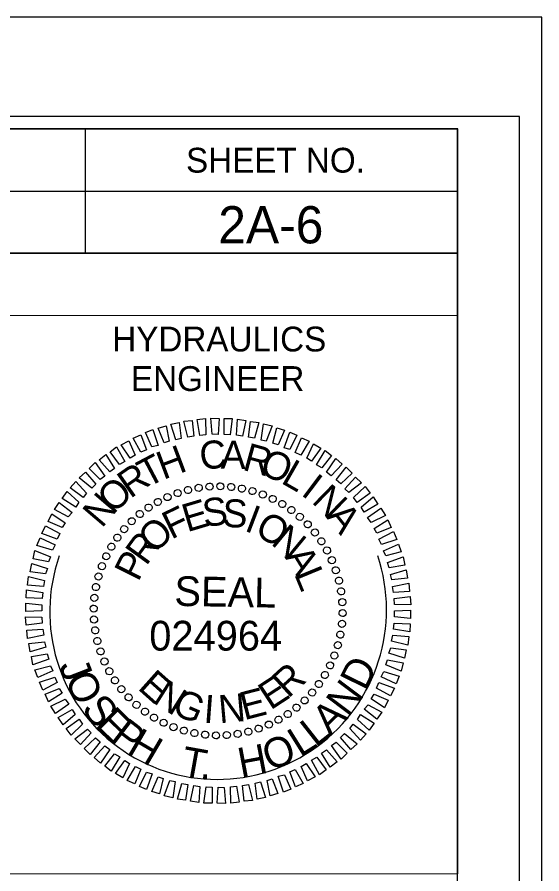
# Model space of a CAD drawing. Extents: x 1640342 to 1730599, y 538663 to 843747.
# Drawn here: x 1730156.25 to 1730177.39, y 539096.41 to 539130.92 of the extents above; entities that cross this region are included whole.
import ezdxf

# ---------------------------------------------------------------- set-up
doc = ezdxf.new("R2010")
doc.units = 0
for name, color, linetype in [('Sheet Data Field CELL', 7, 'Continuous'), ('Sheet PE Seal Cell', 7, 'Continuous'), ('Sheet Plan CELL', 7, 'Continuous'), ('Sheet Plan Layout CELL', 7, 'Continuous'), ('Sheet Plot Border Inside CELL', 7, 'Continuous'), ('Sheet Plot Border Outside CELL', 7, 'Continuous')]:
    doc.layers.add(name, color=color, linetype=linetype)

msp = doc.modelspace()

# ---------------------------------------------------------------- linework, layer by layer
at = {"layer": 'Sheet PE Seal Cell'}
for p, q in [((1730163.999, 539112.014), (1730163.999, 539112.014)), ((1730164.439, 539112.024), (1730164.439, 539112.024)), ((1730164.879, 539111.994), (1730164.879, 539111.994)), ((1730162.709, 539111.754), (1730162.709, 539111.754)), ((1730163.129, 539111.874), (1730163.129, 539111.874)), ((1730163.569, 539111.954), (1730163.569, 539111.954)), ((1730165.309, 539111.924), (1730165.309, 539111.924)), ((1730165.729, 539111.834), (1730165.729, 539111.834)), ((1730166.149, 539111.694), (1730166.149, 539111.694)), ((1730161.919, 539111.394), (1730161.919, 539111.394)), ((1730162.309, 539111.594), (1730162.309, 539111.594)), ((1730166.549, 539111.514), (1730166.549, 539111.514)), ((1730166.939, 539111.314), (1730166.939, 539111.314)), ((1730161.539, 539111.164), (1730161.539, 539111.164)), ((1730167.299, 539111.064), (1730167.299, 539111.064)), ((1730160.859, 539110.614), (1730160.859, 539110.614)), ((1730161.189, 539110.914), (1730161.189, 539110.914)), ((1730167.649, 539110.794), (1730167.649, 539110.794)), ((1730160.559, 539110.304), (1730160.559, 539110.304)), ((1730167.959, 539110.494), (1730167.959, 539110.494)), ((1730160.289, 539109.954), (1730160.289, 539109.954)), ((1730168.259, 539110.164), (1730168.259, 539110.164)), ((1730160.039, 539109.594), (1730160.039, 539109.594)), ((1730168.509, 539109.814), (1730168.509, 539109.814)), ((1730168.739, 539109.434), (1730168.739, 539109.434)), ((1730159.839, 539109.204), (1730159.839, 539109.204)), ((1730168.939, 539109.044), (1730168.939, 539109.044)), ((1730159.659, 539108.804), (1730159.659, 539108.804)), ((1730169.099, 539108.644), (1730169.099, 539108.644)), ((1730159.519, 539108.384), (1730159.519, 539108.384)), ((1730169.219, 539108.224), (1730169.219, 539108.224)), ((1730159.429, 539107.964), (1730159.429, 539107.964)), ((1730159.359, 539107.534), (1730159.359, 539107.534)), ((1730169.299, 539107.784), (1730169.299, 539107.784)), ((1730169.359, 539107.354), (1730169.359, 539107.354)), ((1730159.329, 539107.094), (1730159.329, 539107.094)), ((1730169.369, 539106.914), (1730169.369, 539106.914)), ((1730159.339, 539106.654), (1730159.339, 539106.654)), ((1730169.339, 539106.474), (1730169.339, 539106.474)), ((1730159.399, 539106.224), (1730159.399, 539106.224)), ((1730159.479, 539105.784), (1730159.479, 539105.784)), ((1730169.269, 539106.044), (1730169.269, 539106.044)), ((1730169.179, 539105.624), (1730169.179, 539105.624)), ((1730159.599, 539105.364), (1730159.599, 539105.364)), ((1730169.039, 539105.204), (1730169.039, 539105.204)), ((1730159.759, 539104.964), (1730159.759, 539104.964)), ((1730168.859, 539104.804), (1730168.859, 539104.804)), ((1730159.959, 539104.574), (1730159.959, 539104.574)), ((1730168.659, 539104.414), (1730168.659, 539104.414)), ((1730160.189, 539104.194), (1730160.189, 539104.194)), ((1730168.409, 539104.054), (1730168.409, 539104.054)), ((1730160.439, 539103.844), (1730160.439, 539103.844)), ((1730160.739, 539103.514), (1730160.739, 539103.514)), ((1730167.839, 539103.394), (1730167.839, 539103.394)), ((1730168.139, 539103.704), (1730168.139, 539103.704)), ((1730161.049, 539103.214), (1730161.049, 539103.214)), ((1730167.509, 539103.094), (1730167.509, 539103.094)), ((1730161.399, 539102.944), (1730161.399, 539102.944)), ((1730161.759, 539102.694), (1730161.759, 539102.694)), ((1730167.159, 539102.844), (1730167.159, 539102.844)), ((1730162.149, 539102.494), (1730162.149, 539102.494)), ((1730166.389, 539102.414), (1730166.389, 539102.414)), ((1730166.779, 539102.614), (1730166.779, 539102.614)), ((1730162.549, 539102.314), (1730162.549, 539102.314)), ((1730162.969, 539102.174), (1730162.969, 539102.174)), ((1730163.389, 539102.084), (1730163.389, 539102.084)), ((1730163.819, 539102.014), (1730163.819, 539102.014)), ((1730164.259, 539101.984), (1730164.259, 539101.984)), ((1730164.699, 539101.994), (1730164.699, 539101.994)), ((1730165.129, 539102.054), (1730165.129, 539102.054)), ((1730165.569, 539102.134), (1730165.569, 539102.134)), ((1730165.989, 539102.254), (1730165.989, 539102.254))]:
    msp.add_line(p, q, dxfattribs=at)
for points in [[(1730164.109, 539114.114), (1730164.059, 539114.764), (1730164.389, 539114.754), (1730164.349, 539114.104)], [(1730164.589, 539114.104), (1730164.589, 539114.754), (1730164.919, 539114.744), (1730164.829, 539114.094)], [(1730162.169, 539113.764), (1730161.939, 539114.364), (1730162.249, 539114.454), (1730162.379, 539113.834)], [(1730162.649, 539113.894), (1730162.439, 539114.524), (1730162.779, 539114.594), (1730162.859, 539113.944)], [(1730163.129, 539114.004), (1730162.969, 539114.644), (1730163.299, 539114.674), (1730163.369, 539114.034)], [(1730163.609, 539114.064), (1730163.499, 539114.704), (1730163.839, 539114.744), (1730163.849, 539114.094)], [(1730165.089, 539114.074), (1730165.129, 539114.724), (1730165.459, 539114.664), (1730165.329, 539114.034)], [(1730165.569, 539113.994), (1730165.659, 539114.634), (1730165.989, 539114.584), (1730165.809, 539113.964)], [(1730166.079, 539113.884), (1730166.179, 539114.534), (1730166.519, 539114.454), (1730166.289, 539113.834)], [(1730161.239, 539113.394), (1730160.919, 539113.954), (1730161.229, 539114.094), (1730161.459, 539113.484)], [(1730161.679, 539113.604), (1730161.419, 539114.184), (1730161.719, 539114.304), (1730161.929, 539113.664)], [(1730166.559, 539113.754), (1730166.709, 539114.374), (1730167.019, 539114.274), (1730166.769, 539113.684)], [(1730167.009, 539113.574), (1730167.239, 539114.204), (1730167.519, 539114.084), (1730167.239, 539113.504)], [(1730160.809, 539113.154), (1730160.439, 539113.694), (1730160.749, 539113.854), (1730160.999, 539113.274)], [(1730167.459, 539113.384), (1730167.709, 539113.974), (1730168.019, 539113.834), (1730167.679, 539113.274)], [(1730167.919, 539113.154), (1730168.189, 539113.724), (1730168.489, 539113.554), (1730168.109, 539113.034)], [(1730160.369, 539112.904), (1730159.999, 539113.414), (1730160.259, 539113.604), (1730160.589, 539113.024)], [(1730168.309, 539112.884), (1730168.659, 539113.464), (1730168.919, 539113.254), (1730168.529, 539112.764)], [(1730159.989, 539112.604), (1730159.559, 539113.084), (1730159.829, 539113.294), (1730160.179, 539112.734)], [(1730168.719, 539112.584), (1730169.089, 539113.134), (1730169.349, 539112.914), (1730168.909, 539112.444)], [(1730159.589, 539112.294), (1730159.149, 539112.734), (1730159.389, 539112.974), (1730159.779, 539112.434)], [(1730169.099, 539112.274), (1730169.509, 539112.794), (1730169.749, 539112.554), (1730169.289, 539112.124)], [(1730159.259, 539111.944), (1730158.749, 539112.354), (1730158.999, 539112.584), (1730159.419, 539112.104)], [(1730169.459, 539111.924), (1730169.889, 539112.394), (1730170.129, 539112.154), (1730169.609, 539111.764)], [(1730158.909, 539111.564), (1730158.389, 539111.954), (1730158.609, 539112.214), (1730159.049, 539111.744)], [(1730169.809, 539111.564), (1730170.269, 539112.014), (1730170.479, 539111.744), (1730169.949, 539111.364)], [(1730158.609, 539111.184), (1730158.069, 539111.524), (1730158.259, 539111.814), (1730158.739, 539111.374)], [(1730158.309, 539110.784), (1730157.749, 539111.084), (1730157.949, 539111.364), (1730158.469, 539110.964)], [(1730170.109, 539111.174), (1730170.599, 539111.594), (1730170.789, 539111.304), (1730170.229, 539110.984)], [(1730170.369, 539110.764), (1730170.899, 539111.144), (1730171.089, 539110.844), (1730170.509, 539110.564)], [(1730158.069, 539110.354), (1730157.499, 539110.604), (1730157.649, 539110.914), (1730158.189, 539110.544)], [(1730170.629, 539110.324), (1730171.189, 539110.674), (1730171.319, 539110.364), (1730170.749, 539110.134)], [(1730157.869, 539109.894), (1730157.249, 539110.124), (1730157.399, 539110.434), (1730157.969, 539110.114)], [(1730157.669, 539109.454), (1730157.049, 539109.634), (1730157.179, 539109.944), (1730157.779, 539109.664)], [(1730170.829, 539109.894), (1730171.419, 539110.194), (1730171.549, 539109.874), (1730170.929, 539109.674)], [(1730171.009, 539109.424), (1730171.619, 539109.684), (1730171.729, 539109.374), (1730171.109, 539109.214)], [(1730157.519, 539108.974), (1730156.899, 539109.104), (1730156.969, 539109.434), (1730157.599, 539109.184)], [(1730157.389, 539108.494), (1730156.769, 539108.574), (1730156.839, 539108.914), (1730157.469, 539108.704)], [(1730171.169, 539108.944), (1730171.809, 539109.174), (1730171.869, 539108.844), (1730171.239, 539108.734)], [(1730171.289, 539108.464), (1730171.919, 539108.654), (1730171.979, 539108.314), (1730171.349, 539108.254)], [(1730157.309, 539107.984), (1730156.669, 539108.044), (1730156.709, 539108.384), (1730157.359, 539108.224)], [(1730157.259, 539107.504), (1730156.609, 539107.524), (1730156.629, 539107.854), (1730157.279, 539107.744)], [(1730171.379, 539107.984), (1730172.029, 539108.124), (1730172.059, 539107.784), (1730171.419, 539107.744)], [(1730171.439, 539107.504), (1730172.089, 539107.584), (1730172.109, 539107.244), (1730171.459, 539107.264)], [(1730157.249, 539107.004), (1730156.599, 539106.974), (1730156.599, 539107.314), (1730157.249, 539107.244)], [(1730171.449, 539107.004), (1730172.099, 539107.034), (1730172.099, 539106.694), (1730171.449, 539106.764)], [(1730157.259, 539106.504), (1730156.609, 539106.424), (1730156.589, 539106.764), (1730157.239, 539106.744)], [(1730171.439, 539106.504), (1730172.089, 539106.484), (1730172.069, 539106.154), (1730171.419, 539106.264)], [(1730157.319, 539106.024), (1730156.669, 539105.884), (1730156.639, 539106.224), (1730157.279, 539106.264)], [(1730171.389, 539106.024), (1730172.029, 539105.964), (1730171.989, 539105.624), (1730171.339, 539105.784)], [(1730157.409, 539105.544), (1730156.779, 539105.354), (1730156.719, 539105.694), (1730157.349, 539105.754)], [(1730171.309, 539105.514), (1730171.929, 539105.434), (1730171.859, 539105.094), (1730171.229, 539105.304)], [(1730157.529, 539105.064), (1730156.889, 539104.834), (1730156.829, 539105.164), (1730157.459, 539105.274)], [(1730157.689, 539104.584), (1730157.079, 539104.324), (1730156.969, 539104.634), (1730157.589, 539104.794)], [(1730171.179, 539105.034), (1730171.799, 539104.904), (1730171.729, 539104.574), (1730171.099, 539104.824)], [(1730171.029, 539104.554), (1730171.649, 539104.374), (1730171.519, 539104.064), (1730170.919, 539104.344)], [(1730157.869, 539104.114), (1730157.279, 539103.814), (1730157.149, 539104.134), (1730157.769, 539104.334)], [(1730170.829, 539104.114), (1730171.449, 539103.884), (1730171.299, 539103.574), (1730170.729, 539103.894)], [(1730158.069, 539103.684), (1730157.509, 539103.334), (1730157.379, 539103.644), (1730157.949, 539103.874)], [(1730158.329, 539103.244), (1730157.799, 539102.864), (1730157.609, 539103.164), (1730158.189, 539103.444)], [(1730170.629, 539103.654), (1730171.199, 539103.404), (1730171.049, 539103.094), (1730170.509, 539103.464)], [(1730158.589, 539102.834), (1730158.099, 539102.414), (1730157.909, 539102.704), (1730158.469, 539103.024)], [(1730170.389, 539103.224), (1730170.949, 539102.924), (1730170.749, 539102.644), (1730170.229, 539103.044)], [(1730170.089, 539102.824), (1730170.629, 539102.484), (1730170.439, 539102.194), (1730169.959, 539102.634)], [(1730158.889, 539102.444), (1730158.429, 539101.994), (1730158.219, 539102.264), (1730158.749, 539102.644)], [(1730169.789, 539102.444), (1730170.309, 539102.054), (1730170.089, 539101.794), (1730169.649, 539102.264)], [(1730159.239, 539102.084), (1730158.809, 539101.614), (1730158.569, 539101.854), (1730159.089, 539102.244)], [(1730169.439, 539102.064), (1730169.949, 539101.654), (1730169.699, 539101.424), (1730169.279, 539101.904)], [(1730159.599, 539101.734), (1730159.189, 539101.214), (1730158.949, 539101.454), (1730159.409, 539101.884)], [(1730169.109, 539101.714), (1730169.549, 539101.274), (1730169.309, 539101.034), (1730168.919, 539101.574)], [(1730159.979, 539101.424), (1730159.609, 539100.874), (1730159.349, 539101.094), (1730159.789, 539101.564)], [(1730168.709, 539101.404), (1730169.139, 539100.924), (1730168.869, 539100.714), (1730168.519, 539101.274)], [(1730160.389, 539101.124), (1730160.039, 539100.544), (1730159.779, 539100.754), (1730160.169, 539101.244)], [(1730160.779, 539100.854), (1730160.509, 539100.284), (1730160.209, 539100.454), (1730160.589, 539100.974)], [(1730168.329, 539101.104), (1730168.699, 539100.594), (1730168.439, 539100.404), (1730168.109, 539100.984)], [(1730161.239, 539100.624), (1730160.989, 539100.034), (1730160.679, 539100.174), (1730161.019, 539100.734)], [(1730167.459, 539100.614), (1730167.779, 539100.054), (1730167.469, 539099.914), (1730167.239, 539100.524)], [(1730167.889, 539100.854), (1730168.259, 539100.314), (1730167.949, 539100.154), (1730167.699, 539100.734)], [(1730161.689, 539100.434), (1730161.459, 539099.804), (1730161.179, 539099.924), (1730161.459, 539100.504)], [(1730162.139, 539100.254), (1730161.989, 539099.634), (1730161.679, 539099.734), (1730161.929, 539100.324)], [(1730167.019, 539100.404), (1730167.279, 539099.824), (1730166.979, 539099.704), (1730166.769, 539100.344)], [(1730162.619, 539100.124), (1730162.519, 539099.474), (1730162.179, 539099.554), (1730162.409, 539100.174)], [(1730163.129, 539100.014), (1730163.039, 539099.374), (1730162.709, 539099.424), (1730162.889, 539100.044)], [(1730163.609, 539099.934), (1730163.569, 539099.284), (1730163.239, 539099.344), (1730163.369, 539099.974)], [(1730164.109, 539099.904), (1730164.109, 539099.254), (1730163.779, 539099.264), (1730163.869, 539099.914)], [(1730165.089, 539099.944), (1730165.199, 539099.304), (1730164.859, 539099.264), (1730164.849, 539099.914)], [(1730165.569, 539100.004), (1730165.729, 539099.364), (1730165.399, 539099.334), (1730165.329, 539099.974)], [(1730166.049, 539100.114), (1730166.259, 539099.484), (1730165.919, 539099.414), (1730165.839, 539100.064)], [(1730166.529, 539100.244), (1730166.759, 539099.644), (1730166.449, 539099.554), (1730166.319, 539100.174)], [(1730164.589, 539099.894), (1730164.639, 539099.244), (1730164.309, 539099.254), (1730164.349, 539099.904)]]:
    msp.add_lwpolyline(points, close=True, dxfattribs=at)
for centre, major_axis in [((1730163.136, 539111.871), (-0.035, 0.14)), ((1730163.565, 539111.958), (-0.023, 0.142)), ((1730163.999, 539112.008), (-0.01, 0.144)), ((1730164.437, 539112.019), (0.003, 0.144)), ((1730164.874, 539111.993), (0.015, 0.143)), ((1730165.306, 539111.928), (0.027, 0.141)), ((1730165.732, 539111.826), (0.04, 0.138)), ((1730162.309, 539111.586), (-0.059, 0.132)), ((1730162.716, 539111.747), (-0.047, 0.136)), ((1730166.147, 539111.687), (0.052, 0.134)), ((1730166.548, 539111.512), (0.063, 0.129)), ((1730161.544, 539111.162), (-0.081, 0.119)), ((1730161.918, 539111.391), (-0.07, 0.126)), ((1730166.933, 539111.304), (0.074, 0.123)), ((1730161.193, 539110.902), (-0.091, 0.112)), ((1730167.298, 539111.062), (0.085, 0.116)), ((1730160.865, 539110.612), (-0.1, 0.104)), ((1730167.64, 539110.79), (0.094, 0.109)), ((1730167.958, 539110.488), (0.104, 0.1)), ((1730160.564, 539110.295), (-0.109, 0.094)), ((1730168.247, 539110.161), (0.112, 0.091)), ((1730160.291, 539109.952), (-0.116, 0.085)), ((1730168.508, 539109.809), (0.119, 0.081)), ((1730160.05, 539109.587), (-0.123, 0.074)), ((1730168.736, 539109.436), (0.126, 0.07)), ((1730159.841, 539109.203), (-0.129, 0.063)), ((1730159.666, 539108.802), (-0.134, 0.052)), ((1730168.932, 539109.044), (0.132, 0.059)), ((1730159.528, 539108.387), (-0.138, 0.04)), ((1730169.092, 539108.637), (0.136, 0.047)), ((1730169.216, 539108.218), (0.14, 0.035)), ((1730159.425, 539107.961), (-0.141, 0.027)), ((1730169.304, 539107.789), (0.142, 0.023)), ((1730159.361, 539107.528), (-0.143, 0.015)), ((1730169.353, 539107.354), (0.144, 0.01)), ((1730159.334, 539107.092), (-0.144, 0.003)), ((1730169.365, 539106.916), (0.144, -0.003)), ((1730159.346, 539106.654), (-0.144, -0.01)), ((1730169.338, 539106.48), (0.143, -0.015)), ((1730159.395, 539106.219), (-0.142, -0.023)), ((1730169.273, 539106.047), (0.141, -0.027)), ((1730159.482, 539105.791), (-0.14, -0.035)), ((1730169.171, 539105.621), (0.138, -0.04)), ((1730159.607, 539105.371), (-0.136, -0.047)), ((1730159.767, 539104.964), (-0.132, -0.059)), ((1730169.032, 539105.206), (0.134, -0.052)), ((1730168.858, 539104.805), (0.129, -0.063)), ((1730159.962, 539104.572), (-0.126, -0.07)), ((1730168.649, 539104.421), (0.123, -0.074)), ((1730160.191, 539104.199), (-0.119, -0.081)), ((1730168.407, 539104.056), (0.116, -0.085)), ((1730160.451, 539103.847), (-0.112, -0.091)), ((1730168.135, 539103.713), (0.109, -0.094)), ((1730160.741, 539103.52), (-0.104, -0.1)), ((1730161.059, 539103.218), (-0.094, -0.109)), ((1730167.834, 539103.396), (0.1, -0.104)), ((1730161.401, 539102.946), (-0.085, -0.116)), ((1730167.506, 539103.106), (0.091, -0.112)), ((1730161.766, 539102.704), (-0.074, -0.123)), ((1730166.781, 539102.617), (0.07, -0.126)), ((1730167.154, 539102.846), (0.081, -0.119)), ((1730162.15, 539102.496), (-0.063, -0.129)), ((1730162.552, 539102.321), (-0.052, -0.134)), ((1730162.967, 539102.182), (-0.04, -0.138)), ((1730165.982, 539102.261), (0.047, -0.136)), ((1730166.39, 539102.422), (0.059, -0.132)), ((1730163.392, 539102.08), (-0.027, -0.141)), ((1730163.825, 539102.016), (-0.015, -0.143)), ((1730164.262, 539101.989), (-0.003, -0.144)), ((1730164.699, 539102), (0.01, -0.144)), ((1730165.134, 539102.05), (0.023, -0.142)), ((1730165.563, 539102.137), (0.035, -0.14))]:
    msp.add_ellipse(centre, major_axis=major_axis, ratio=0.999708, dxfattribs=at)
at = {"layer": 'Sheet Plan CELL'}
for p, q in [((1730158.985, 539126.405), (1730158.995, 539121.405)), ((1730133.98, 539123.91), (1730173.99, 539123.908)), ((1730133.983, 539121.403), (1730173.99, 539121.408)), ((1730133.983, 539121.403), (1730173.99, 539121.408))]:
    msp.add_line(p, q, dxfattribs=at)
for points in [[(1730173.998, 539126.418), (1729873.99, 539126.418), (1729873.99, 538916.418), (1730173.993, 538916.418)], [(1730133.983, 539126.42), (1730173.998, 539126.418), (1730173.99, 539121.408), (1730133.983, 539121.403)], [(1730153.993, 539118.905), (1730173.99, 539118.908), (1730173.993, 539096.405), (1730153.993, 539096.403)]]:
    msp.add_lwpolyline(points, close=True, dxfattribs=at)
at = {"layer": 'Sheet Plan Layout CELL'}
msp.add_lwpolyline([(1730126.14, 539084.12), (1730173.995, 539084.12), (1730174, 539126.418), (1730126.14, 539126.418)], close=True, dxfattribs=at)
at = {"layer": 'Sheet Plot Border Inside CELL'}
msp.add_lwpolyline([(1729843.293, 538915.915), (1730176.49, 538915.918), (1730176.493, 539126.915), (1729843.293, 539126.915)], close=True, dxfattribs=at)
at = {"layer": 'Sheet Plot Border Outside CELL'}
msp.add_lwpolyline([(1729840.693, 538911.915), (1730177.393, 538911.915), (1730177.393, 539130.915), (1729840.693, 539130.915)], close=True, dxfattribs=at)
msp.add_ellipse((1730164.349, 539107.004), major_axis=(4.509, 5.104), ratio=0.993455, start_param=1.958957, end_param=5.764947, dxfattribs=at)

# ---------------------------------------------------------------- texts
at = {"layer": 'Sheet Data Field CELL'}
msp.add_text('2A-6', height=1.5, rotation=0, dxfattribs=at).set_placement((1730164.353, 539121.803))
at = {"layer": 'Sheet PE Seal Cell'}
for s, height, rotation, p in [('C', 1.128, 6.2199, (1730163.659, 539112.674)), ('A', 1.128, 359.0203, (1730164.449, 539112.734)), ('R', 1.128, 344.6211, (1730165.289, 539112.694)), ('H', 1.128, 20.6195, (1730162.139, 539112.274)), ('O', 1.128, 337.4212, (1730165.959, 539112.544)), ('T', 1.128, 27.8198, (1730161.489, 539111.944)), ('L', 1.128, 330.2209, (1730166.839, 539112.174)), ('R', 1.128, 35.0205, (1730160.809, 539111.504)), ('I', 1.128, 323.0201, (1730167.649, 539111.694)), ('O', 1.128, 42.2217, (1730160.119, 539110.884)), ('N', 1.128, 315.8189, (1730168.079, 539111.384)), ('N', 1.128, 49.4235, (1730159.659, 539110.304)), ('E', 1.128, 16.6111, (1730163.099, 539110.164)), ('S', 1.128, 7.2556, (1730163.789, 539110.374)), ('S', 1.128, 357.9004, (1730164.509, 539110.384)), ('F', 1.128, 25.967, (1730162.459, 539109.864)), ('I', 1.128, 339.1896, (1730165.369, 539110.244)), ('A', 1.128, 308.6172, (1730168.669, 539110.794)), ('O', 1.128, 44.6812, (1730161.799, 539109.274)), ('O', 1.128, 329.8335, (1730165.769, 539110.104)), ('N', 1.128, 320.4766, (1730166.439, 539109.704)), ('R', 1.128, 54.0397, (1730161.449, 539108.784)), ('P', 1.128, 63.3989, (1730161.129, 539108.144)), ('A', 1.128, 301.7603, (1730167.009, 539109.184)), ('L', 1.128, 292.4008, (1730167.399, 539108.494)), ('SEAL', 1.1996, 359, (1730162.579, 539107.204)), ('D', 1.2, 63.6039, (1730170.285, 539103.738)), ('J', 1.2, 291.2124, (1730157.911, 539104.798)), ('R', 1.128, 42.4814, (1730167.169, 539103.454)), ('O', 1.2, 296.4669, (1730158.135, 539104.221)), ('E', 1.128, 318.2769, (1730161.069, 539103.874)), ('E', 1.128, 33.1241, (1730166.459, 539102.984)), ('N', 1.128, 327.634, (1730161.669, 539103.334)), ('N', 1.2, 53.0513, (1730169.575, 539102.696)), ('G', 1.128, 336.9902, (1730162.429, 539102.884)), ('E', 1.128, 14.4118, (1730165.399, 539102.594)), ('S', 1.2, 308.0413, (1730158.806, 539103.039)), ('I', 1.128, 355.7012, (1730163.739, 539102.504)), ('N', 1.128, 5.0564, (1730164.409, 539102.474)), ('E', 1.2, 315.3853, (1730159.35, 539102.37)), ('A', 1.2, 44.3588, (1730168.854, 539101.946)), ('P', 1.2, 322.5143, (1730159.955, 539101.792)), ('L', 1.2, 38.1871, (1730168.277, 539101.484)), ('H', 1.2, 329.641, (1730160.627, 539101.294)), ('L', 1.2, 32.0108, (1730167.655, 539101.087)), ('H', 1.2, 10.7371, (1730165.267, 539100.275)), ('O', 1.2, 20.6113, (1730166.41, 539100.54)), ('T', 1.2, 349.8271, (1730162.805, 539100.374)), ('.', 1.2, 356.6032, (1730163.595, 539100.244))]:
    msp.add_text(s, height=height, rotation=rotation, dxfattribs=at).set_placement(p)
msp.add_text('024964', height=1.1996, dxfattribs=at).set_placement((1730161.574, 539105.402))
at = {"layer": 'Sheet Plan CELL'}
for s, p in [('SHEET NO.', (1730163.055, 539124.653)), ('HYDRAULICS', (1730160.085, 539117.45)), ('ENGINEER', (1730160.838, 539115.858))]:
    msp.add_text(s, height=1, rotation=0, dxfattribs=at).set_placement(p)

doc.saveas('drawing.dxf')
